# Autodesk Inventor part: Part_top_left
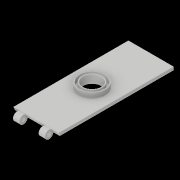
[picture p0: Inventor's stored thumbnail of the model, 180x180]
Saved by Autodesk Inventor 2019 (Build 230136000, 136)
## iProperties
Created: 2019-08
Part Number: Part_top_left
Material: 常规
Document SubType Name: Modeling
Designer: YOGA3
Density: 1 g/cm^3
Appearance: 默认
Author: YOGA3
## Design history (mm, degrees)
sketch "草图1"
  geometry: L1 (-22, 57.5)-(22, 57.5); L2 (22, 57.5)-(22, -57.5); L3 (22, -57.5)-(-22, -57.5); L4 (-22, -57.5)-(-22, 57.5); L5 (-22, 57.5)-(22, -57.5); L6 (22, 57.5)-(-22, -57.5); 1 further point
  constraints: 12 end point, 2 midpoint, 2 parallel, 1 horizontal, 1 perpendicular
  dimensions: "d0" = 44 distance of L2.end L3.end; "d1" = 115 distance of L1.end L2.end
extrude "拉伸1" new body sketch "草图1" distance "d2" = 3; taper "d3" = 0 deg
sketch "草图2"
  geometry: C1 r 2 at (0, 0); 1 further point
  constraints: 1 centre point
  dimensions: "d4" = 4 diameter of C1
extrude "拉伸2" cut sketch "草图2" distance "d5" = 44; taper "d6" = 0 deg
node "工作平面1"
node "工作平面2"
sketch "草图3"
  geometry: C1 r 4 at (-115, 0); C2 r 2 at (-115, 0); A1 r 2 centre (-115, 0) between (-113, 0) and (-115, 2) reference; 1 further point
  constraints: 2 centre point, 2 coincident
  dimensions: "d9" = 8 diameter of C1
extrude "拉伸3" join sketch "草图3" distance "d10" = 6; taper "d11" = 0 deg
sketch "草图4"
  geometry: C1 r 4 at (115, 0); A1 r 2 centre (115, 0) between (115, 2) and (113, 0) reference; 2 further points
  constraints: 2 coincident, 1 centre point, 1 vertical alignment, 2 other
extrude "拉伸4" join sketch "草图4" distance "d12" = 6; taper "d13" = 0 deg
sketch "草图14"
  geometry: C1 r 4 at (-115, 0); A1 r 2 centre (-115, 0) between (-113, 0) and (-115, 2) reference; 1 further point
  constraints: 1 centre point, 1 coincident
extrude "拉伸12" cut sketch "草图14" distance "d39" = 6.5; taper "d40" = 0 deg
sketch "草图15"
  geometry: C1 r 4 at (115, 0); A1 r 2 centre (115, 0) between (115, 2) and (113, 0) reference; 1 further point
  constraints: 1 centre point, 1 coincident
extrude "拉伸13" cut sketch "草图15" distance "d41" = 6.5; taper "d42" = 0 deg
sketch "草图16"
  geometry: C1 r 4 at (-115, 0); A1 r 2 centre (-115, 0) between (-115, 2) and (-113, 0) reference; 1 further point
  constraints: 1 centre point, 1 coincident
extrude "拉伸14" cut sketch "草图16" distance "d43" = 19; taper "d44" = 0 deg
sketch "草图26"
  geometry: L1 (0, 0)-(10.392, 0); C1 r 9 at (0, 0); 1 further point
  constraints: 2 coincident, 2 end point, 1 centre point, 1 horizontal
  dimensions: "d101" = 18 diameter of C1
extrude "拉伸20" cut sketch "草图26" distance "d73" = 3; taper "d74" = 0 deg
sketch "Sketch33"
  geometry: C1 r 9 at (0, 0); C2 r 12.1 at (0, 0); C3 r 9 at (0, 0) reference; C4 r 9.9 at (0, 0); C5 r 13 at (0, 0); 1 further point
  constraints: 4 centre point, 4 coincident, 1 concentric
  dimensions: "d102" = 2.2 radial gap between concentric circles of C2 C4; "d103" = 0.9 radial gap between concentric circles of C5 C2; "d104" = 0.9 radial gap between concentric circles of C1 C4
extrude "Extrusion25" join sketch "Sketch33" distance "d99" = 5; taper "d100" = 0 deg
sketch "草图27"
  geometry: L1 (-10.392, 0)-(-5.196, 9); L2 (-5.196, 9)-(5.196, 9); L3 (5.196, 9)-(10.392, 0); L4 (10.392, 0)-(5.196, -9); L5 (5.196, -9)-(-5.196, -9); L6 (-5.196, -9)-(-10.392, 0); L7 (0, 0)-(-10.392, 0); C1 r 9 at (0, 0); 1 further point
  constraints: 14 end point, 2 coincident, 1 centre point, 1 horizontal, 13 other
  dimensions: "d75" = 18 diameter of C1; "d94" = 18 distance between parallel lines of L5 L2
extrude "拉伸21" cut sketch "草图27" distance "d76" = 4; taper "d77" = 0 deg
sketch "草图28"
  geometry: L1 (-5.196, -9)-(-10.392, 0) reference; L2 (5.196, 9)-(10.392, 0) reference; L3 (-10.392, 0)-(10.392, 0); C1 r 5 at (0, 0); 1 further point
  constraints: 2 end point, 1 centre point, 1 coincident, 1 horizontal, 1 midpoint
  dimensions: "d95" = 10 diameter of C1
extrude "拉伸22" cut sketch "草图28" distance "d79" = 5; taper "d80" = 0 deg
sketch "草图31"
  geometry: L1 (-6, 50)-(6, 50); L2 (6, 50)-(6, 34); L3 (6, 34)-(-6, 34); L4 (-6, 34)-(-6, 50); L5 (-6, 50)-(6, 34); L6 (6, 50)-(-6, 34); 3 further points
  constraints: 12 end point, 2 midpoint, 2 parallel, 1 horizontal, 1 perpendicular
  dimensions: "d81" = 12 distance of L2.end L3.end; "d82" = 16 distance of L1.end L2.end; "d83" = 50 distance from line of point (0, 0) L1
extrude "拉伸23" cut sketch "草图31" distance "d84" = 3; taper "d85" = 0 deg
sketch "草图32"
  geometry: L1 (18, 5)-(26, 5); L2 (26, 5)-(26, 1); L3 (26, 1)-(18, 1); L4 (18, 1)-(18, 5); L5 (13, 3)-(31, 3) reference; L6 (18, 5)-(26, 1); L7 (26, 5)-(18, 1); 2 further points
  constraints: 12 end point, 3 midpoint, 2 parallel, 1 horizontal, 1 perpendicular
  dimensions: "d86" = 8 distance of L2.end L3.end; "d87" = 4 distance of L1.end L2.end
extrude "拉伸24" cut sketch "草图32" distance "d88" = 37.5; taper "d89" = 0 deg; dims "d90" = 7, "d91" = 0
node "实体1"
other parameters: "d7" = -6.5, "d8" = -6.5
